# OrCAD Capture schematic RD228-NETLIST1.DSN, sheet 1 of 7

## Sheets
1 7: size A3
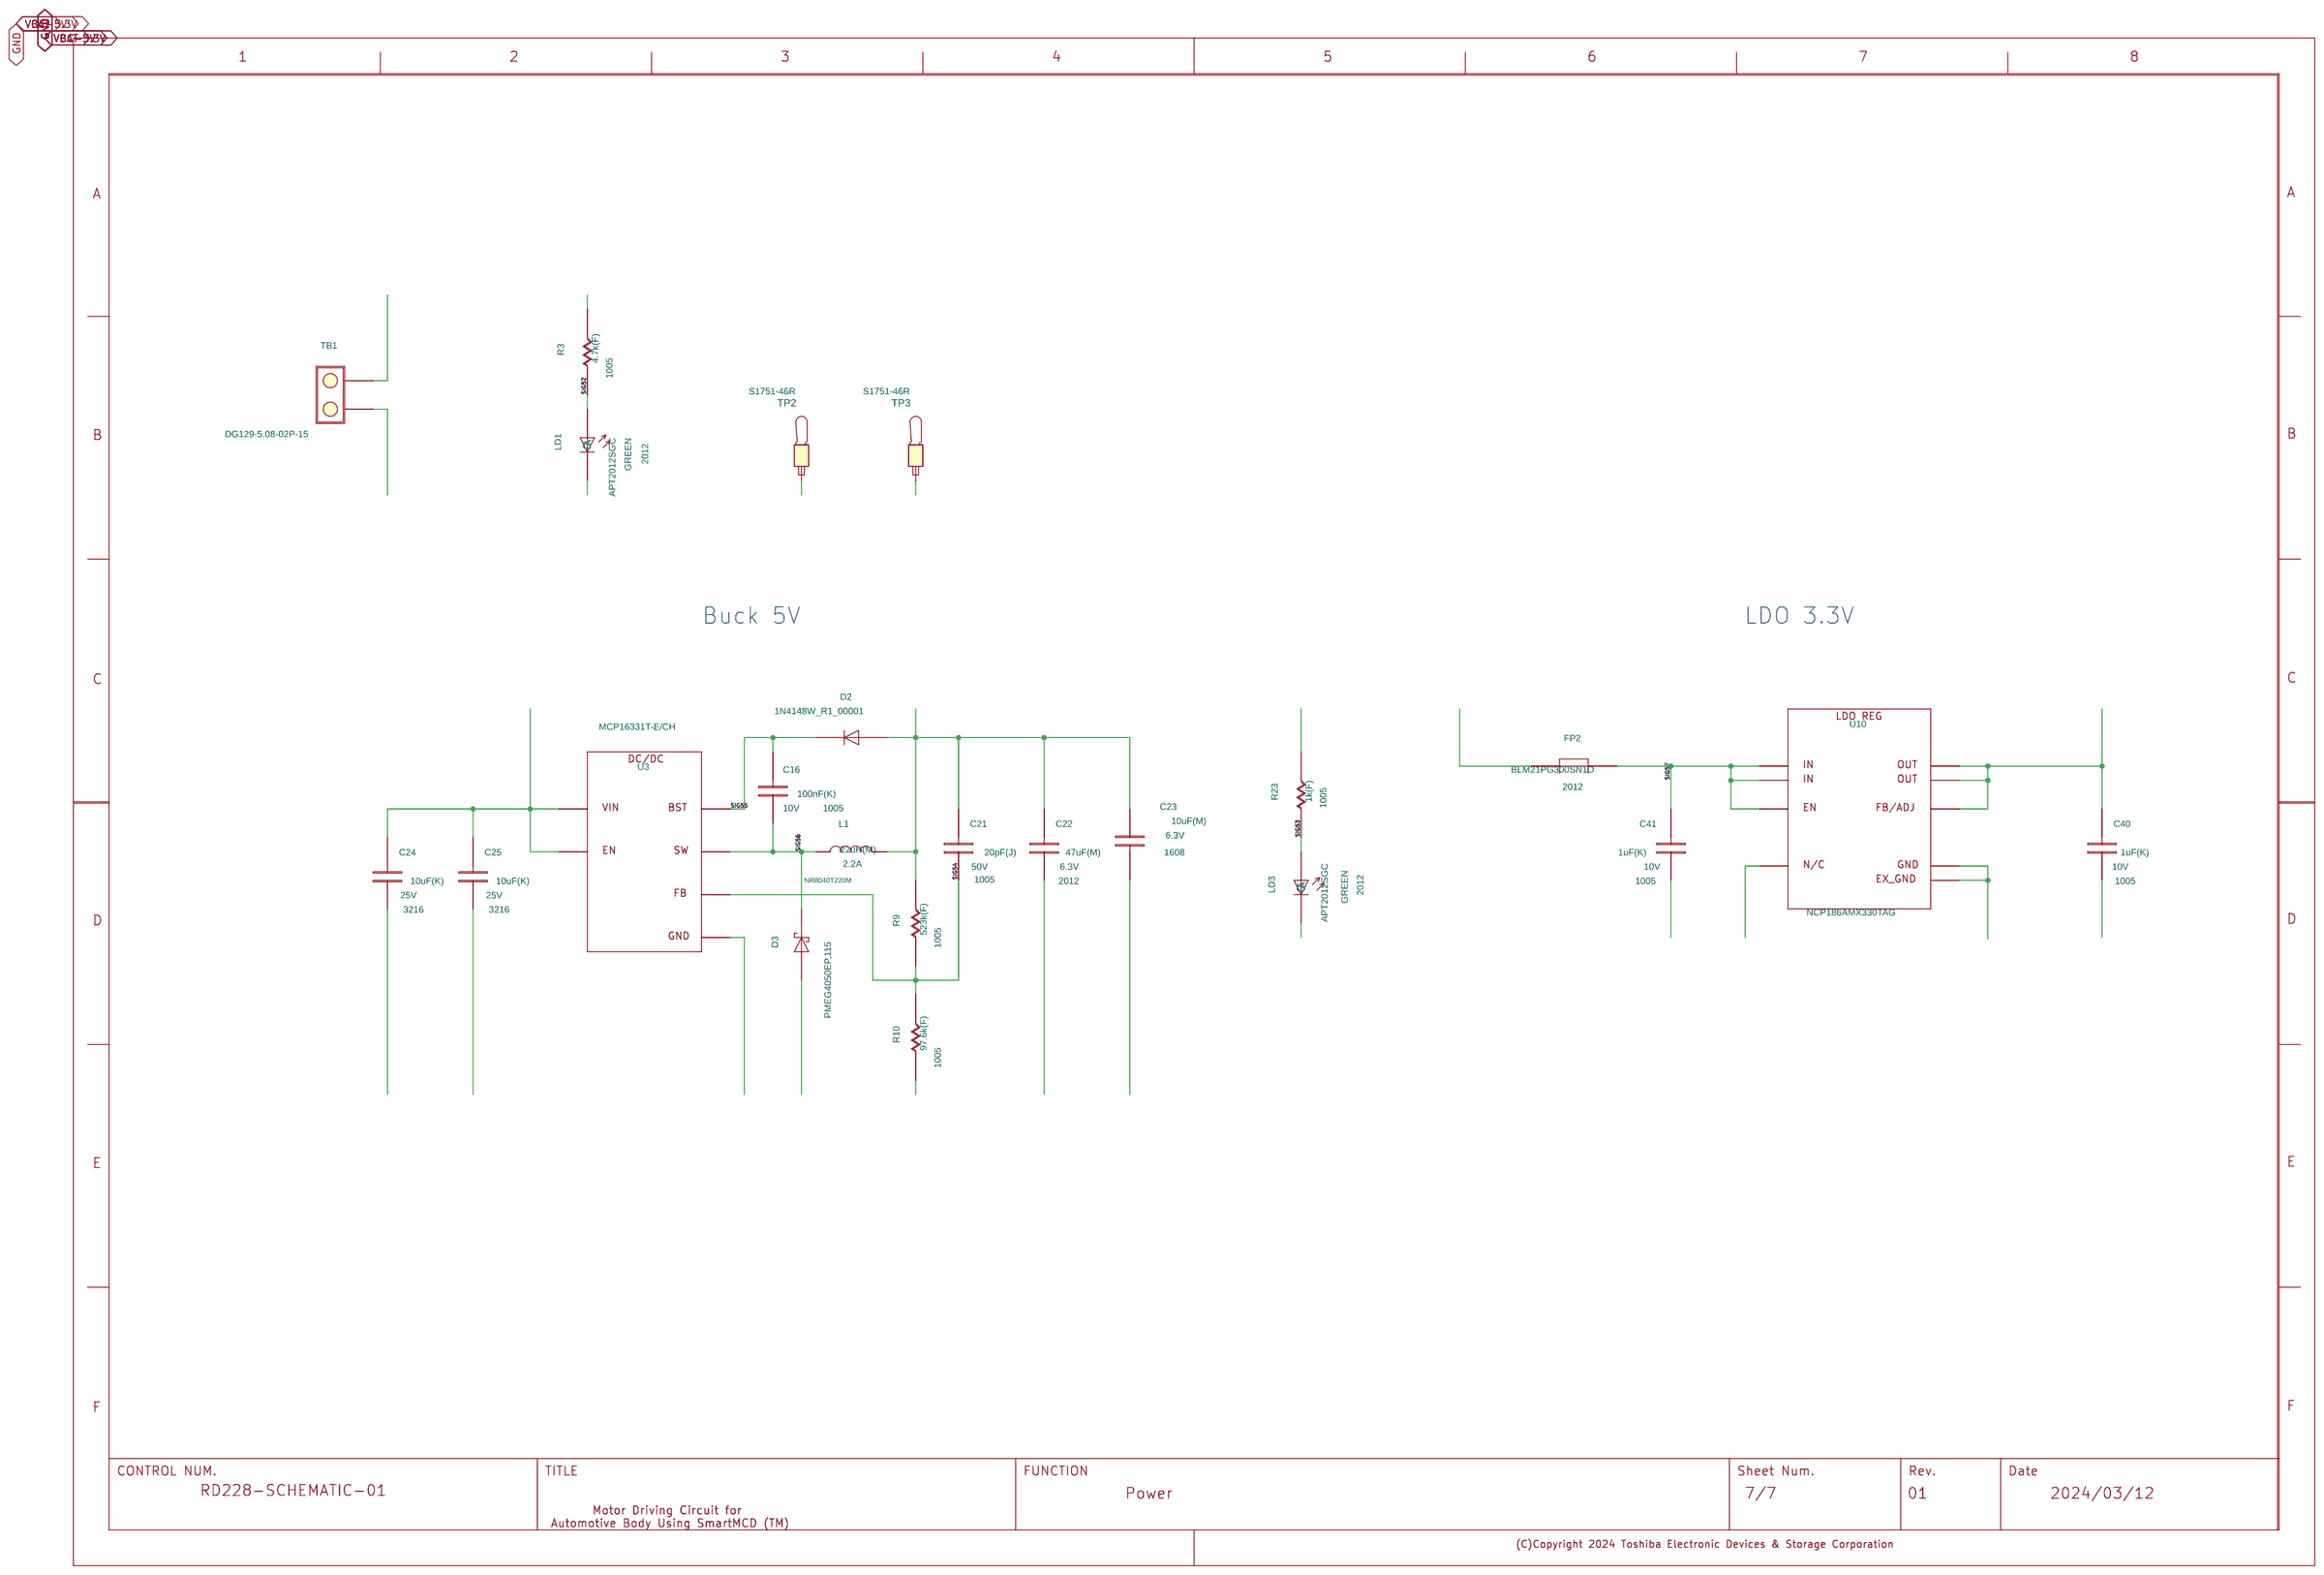
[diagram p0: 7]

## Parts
C16  100nF  [CAPC1005X55N-0402-NoOverlay]
C21  20pF  [CAPC1005X55N-0402-NoOverlay]
C22  47ƒÊF  [CAPC2013X100N-0805-NoOverlay]
C23  10ƒÊF  [CAPC1608X55N-0603-NoOverlay]
C24  10ƒÊF  [CAPC3216X140N-1206-NoOverlay]
C25  10ƒÊF  [CAPC3216X140N-1206-NoOverlay]
C40  1ƒÊF  [CAPC1005X55N-0402-NoOverlay]
C41  1ƒÊF  [CAPC1005X55N-0402-NoOverlay]
D2  NA  [SOD3716X135N-NoOverlay]
D3  NA  [DIOM5127X229N-SOD128-NoOverlay]
FP2  FERRITE  [INDC2213X140N-0805-NOOVERLAY]
L1  L
LD1  PWR  [DIOGREENC2013X120N-0805-NoOverlay]
LD3  3.3V  [DIOGREENC2013X120N-0805-NoOverlay]
R3  4.7k  [RESC1005X40N-0402-NOOVERLAY]
R9  523k  [RESC1005X40N-0402-NOOVERLAY]
R10  97.6k  [RESC1005X40N-0402-NOOVERLAY]
R23  1k  [RESC1005X40N-0402-NOOVERLAY]
TB1  DG129-5.08-02P-15  [SCREW_TERMINAL-5_08-F-2]
TP2  NA
TP3  NA
U3  MCP16331T  [SOT95P275X145-6L20N-SOT23-6-NoOverlay]
U10  NA  [SON40P120X45_HS-9N]
U?#7  WAKU_DEF100

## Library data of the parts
C16 = C: ASSEMBLY: SMD; AUTHOR: t5459927; BARCODE: 2911010025755; CATEGORY: Capacitors; COMP: Capacitor_Ceramic_C16; COMPONENTNAME: Capacitor_Ceramic_C16_Capacitor_Ceramic_C16; COMPONENTTYPE: 4; DATASHEET URL: http://ds.yuden.co.jp/TYCOMPAS/ut/detail.do?productNo; DATE: 2024/2/16; FAMILY: CERAMIC CAPACITOR; INSTANCENAME: INS4825; LAYOUTNAME: Z-cdca0044-bd23-4216-874f-abd41da06501.cmp23; MANUFACTURER: Taiyo Yuden; MANUFACTURER PART NUMBER: LMK105BJ104KV-F; NUMBER DEVICES IN PACKAGE: 1; PACKAGE CASE: 0402 (1005 Metric); PART TYPE: Capacitors; PIN NAMES ROTATE: True; PIN NAMES VISIBLE: False; PIN NUMBERS VISIBLE: False; RECOMMENDED RATING: Platinum; SAVECOUNT: 0; SIZECODESMD: 1005; TEMPERATURE COEFFICIENT: X5R; TIME: 16:56:57; TOLERANCE: }10%; UPDATEDATE: 2024/2/16; UPDATETIME: 16:56:57; UPDATEUSER: t5459927; VAL1: 100nF(K); VAL2: 10V; VAL3: LMK105BJ104KV-F; VOLTAGE RATED: 10V
C21 = C: ASSEMBLY: SMD; AUTHOR: t5459927; BARCODE: 0100000070406; CATEGORY: Capacitors; COMP: Capacitor_Ceramic_C21; COMPONENTNAME: Capacitor_Ceramic_C21_Capacitor_Ceramic_C21; COMPONENTTYPE: 4; DATASHEET URL: http://www.samsungsem.com/kr/support/product-search/mlcc/CL05C200JB5NNNC.jsp; DATE: 2024/2/16; FAMILY: CERAMIC CAPACITOR; ID: 8; INSTANCENAME: INS4815; ITEM_ID: 6192; LAYOUTNAME: Z-cdca0044-bd23-4216-874f-abd41da06501.cmp11; MANUFACTURER: Samsung Electro-Mechanics America, Inc.; MANUFACTURER PART NUMBER: CL05C200JB5NNNC; NUMBER DEVICES IN PACKAGE: 1; PACKAGE CASE: 0402 (1005 Metric); PART TYPE: Capacitors; PIN NAMES ROTATE: True; PIN NAMES VISIBLE: False; PIN NUMBERS VISIBLE: False; SAVECOUNT: 0; SIZECODESMD: 1005; TEMPERATURE COEFFICIENT: C0G, NP0; TIME: 16:56:43; TOLERANCE: }5%; UPDATEDATE: 2024/2/16; UPDATETIME: 16:56:43; UPDATEUSER: t5459927; VAL1: 20pF(J); VAL2: 50V; VAL3: CL05C200JB5NNNC; VOLTAGE RATED: 50V
C22 = C: ASSEMBLY: SMD; AUTHOR: t5459927; BARCODE: 3500000145772; CATEGORY: Capacitors; COMP: Capacitor_Ceramic_C22; COMPONENTNAME: Capacitor_Ceramic_C22_Capacitor_Ceramic_C22; COMPONENTTYPE: 4; DATASHEET URL: http://www.yageo.com/documents/recent/UPY-GPHC_X5R_4V-to-50V_24.pdf; DATE: 2024/2/16; FAMILY: CERAMIC CAPACITOR; ID: 427; INSTANCENAME: INS4835; ITEM_ID: 12714; LAYOUTNAME: Z-cdca0044-bd23-4216-874f-abd41da06501.cmp3; MANUFACTURER: Yageo; MANUFACTURER PART NUMBER: CC0805MKX5R5BB476; NUMBER DEVICES IN PACKAGE: 1; PACKAGE CASE: 0805 (2012 Metric); PART TYPE: Capacitors; PIN NAMES ROTATE: True; PIN NAMES VISIBLE: False; PIN NUMBERS VISIBLE: False; SAVECOUNT: 0; SIZECODESMD: 2012; TEMPERATURE COEFFICIENT: X5R; TIME: 16:56:48; TOLERANCE: }20%; UPDATEDATE: 2024/2/16; UPDATETIME: 16:56:48; UPDATEUSER: t5459927; VAL1: 47uF(M); VAL2: 6.3V; VAL3: CC0805MKX5R5BB476; VOLTAGE RATED: 6.3V
C23 = C: ASSEMBLY: SMD; AUTHOR: t5459927; BARCODE: 2911010042226; CATEGORY: Capacitors; COMP: Capacitor_Ceramic_C23; COMPONENTNAME: Capacitor_Ceramic_C23_Capacitor_Ceramic_C23; COMPONENTTYPE: 4; DATASHEET URL: http://www.samsungsem.com/kr/support/product-search/mlcc/CL10A106MQ8NNNL.jsp; DATE: 2024/2/16; FAMILY: CERAMIC CAPACITOR; ID: 31; INSTANCENAME: INS4845; ITEM_ID: 4902; MANUFACTURER: Samsung Electro-Mechanics America, Inc.; MANUFACTURER PART NUMBER: CL10A106MQ8NNNC; NUMBER DEVICES IN PACKAGE: 1; PACKAGE CASE: 0603 (1608 Metric); PART TYPE: Capacitors; PIN NAMES ROTATE: True; PIN NAMES VISIBLE: False; PIN NUMBERS VISIBLE: False; RECOMMENDED RATING: Platinum; SAVECOUNT: 0; SIZECODESMD: 1608; TEMPERATURE COEFFICIENT: X5R; TIME: 16:56:37; TOLERANCE: }20%; UPDATEDATE: 2024/2/16; UPDATETIME: 16:56:37; UPDATEUSER: t5459927; VAL1: 10uF(M); VAL2: 6.3V; VOLTAGE RATED: 6.3V
C24 = C: ASSEMBLY: SMD; AUTHOR: t5459927; BARCODE: 3500000176264; CATEGORY: Capacitors; COMP: Capacitor_Ceramic_C24; COMPONENTNAME: Capacitor_Ceramic_C24_Capacitor_Ceramic_C24; COMPONENTTYPE: 4; DATASHEET URL: https://www.yuden.co.jp/productdata/catalog/mlcc_all_e.pdf; DATE: 2024/2/16; FAMILY: CERAMIC CAPACITOR; ID: 617; INSTANCENAME: INS4865; ITEM_ID: 15761; LAYOUTNAME: Z-cdca0044-bd23-4216-874f-abd41da06501.cmp29; MANUFACTURER: Taiyo Yuden; MANUFACTURER PART NUMBER: TMK316B7106KL-TD; NUMBER DEVICES IN PACKAGE: 1; PACKAGE CASE: 1206 (3216 Metric); PART TYPE: Capacitors; PIN NAMES ROTATE: True; PIN NAMES VISIBLE: False; PIN NUMBERS VISIBLE: False; SAVECOUNT: 0; SIZECODESMD: 3216; TEMPERATURE COEFFICIENT: X7R; TIME: 16:56:41; TOLERANCE: }10%; UPDATEDATE: 2024/2/16; UPDATETIME: 16:56:41; UPDATEUSER: t5459927; VAL1: 10uF(K); VAL2: 25V; VAL3: TMK316B7106KL-TD; VOLTAGE RATED: 25V
C25 = C: ASSEMBLY: SMD; AUTHOR: t5459927; BARCODE: 3500000176264; CATEGORY: Capacitors; COMP: Capacitor_Ceramic_C25; COMPONENTNAME: Capacitor_Ceramic_C25_Capacitor_Ceramic_C25; COMPONENTTYPE: 4; DATASHEET URL: https://www.yuden.co.jp/productdata/catalog/mlcc_all_e.pdf; DATE: 2024/2/16; FAMILY: CERAMIC CAPACITOR; ID: 617; INSTANCENAME: INS4875; ITEM_ID: 15761; LAYOUTNAME: Z-cdca0044-bd23-4216-874f-abd41da06501.cmp26; MANUFACTURER: Taiyo Yuden; MANUFACTURER PART NUMBER: TMK316B7106KL-TD; NUMBER DEVICES IN PACKAGE: 1; PACKAGE CASE: 1206 (3216 Metric); PART TYPE: Capacitors; PIN NAMES ROTATE: True; PIN NAMES VISIBLE: False; PIN NUMBERS VISIBLE: False; SAVECOUNT: 0; SIZECODESMD: 3216; TEMPERATURE COEFFICIENT: X7R; TIME: 16:56:55; TOLERANCE: }10%; UPDATEDATE: 2024/2/16; UPDATETIME: 16:56:55; UPDATEUSER: t5459927; VAL1: 10uF(K); VAL2: 25V; VAL3: TMK316B7106KL-TD; VOLTAGE RATED: 25V
C40 = C: ASSEMBLY: SMD; AUTHOR: t5459927; BARCODE: 2911010025762; CATEGORY: Capacitors; COMP: Capacitor_Ceramic_C40; COMPONENTNAME: Capacitor_Ceramic_C40_Capacitor_Ceramic_C40; COMPONENTTYPE: 4; DATASHEET URL: http://ds.yuden.co.jp/TYCOMPAS/ut/detail.do?productNo; DATE: 2024/2/16; FAMILY: CERAMIC CAPACITOR; ID: 62; INSTANCENAME: INS5645; ITEM_ID: 3485; LAYOUTNAME: Z-cdca0044-bd23-4216-874f-abd41da06501.cmp36; MANUFACTURER: Taiyo Yuden; MANUFACTURER PART NUMBER: LMK105BJ105KV-F; NUMBER DEVICES IN PACKAGE: 1; PACKAGE CASE: 0402 (1005 Metric); PART TYPE: Capacitors; PIN NAMES ROTATE: True; PIN NAMES VISIBLE: False; PIN NUMBERS VISIBLE: False; SAVECOUNT: 0; SIZECODESMD: 1005; TEMPERATURE COEFFICIENT: X5R; TIME: 16:56:39; TOLERANCE: }10%; UPDATEDATE: 2024/2/16; UPDATETIME: 16:56:39; UPDATEUSER: t5459927; VAL1: 1uF(K); VAL2: 10V; VOLTAGE RATED: 10V
C41 = C: ASSEMBLY: SMD; AUTHOR: t5459927; BARCODE: 2911010025762; CATEGORY: Capacitors; COMP: Capacitor_Ceramic_C41; COMPONENTNAME: Capacitor_Ceramic_C41_Capacitor_Ceramic_C41; COMPONENTTYPE: 4; DATASHEET URL: http://ds.yuden.co.jp/TYCOMPAS/ut/detail.do?productNo; DATE: 2024/2/16; FAMILY: CERAMIC CAPACITOR; ID: 62; INSTANCENAME: INS5655; ITEM_ID: 3485; LAYOUTNAME: Z-cdca0044-bd23-4216-874f-abd41da06501.cmp33; MANUFACTURER: Taiyo Yuden; MANUFACTURER PART NUMBER: LMK105BJ105KV-F; NUMBER DEVICES IN PACKAGE: 1; PACKAGE CASE: 0402 (1005 Metric); PART TYPE: Capacitors; PIN NAMES ROTATE: True; PIN NAMES VISIBLE: False; PIN NUMBERS VISIBLE: False; SAVECOUNT: 0; SIZECODESMD: 1005; TEMPERATURE COEFFICIENT: X5R; TIME: 16:56:53; TOLERANCE: }10%; UPDATEDATE: 2024/2/16; UPDATETIME: 16:56:53; UPDATEUSER: t5459927; VAL1: 1uF(K); VAL2: 10V; VAL3: LMK105BJ105KV-F; VOLTAGE RATED: 10V
D2 = DIODE: ASSEMBLY: SMD; BARCODE: 3500000205278; COMP: DIODE_D2; COMPONENTNAME: DIODE_D2_DIODE_D2; COMPONENTTYPE: 4; CURRENT  AVERAGE RECTIFIED: 300mA (DC); DATASHEET URL: https://www.datasheets360.com/pdf/-7889717499515636739; DIODE TYPE: Standard; ID: 469; INSTANCENAME: INS4807; ITEM_ID: 18663; LAYOUTNAME: Z-cdca0044-bd23-4216-874f-abd41da06501.cmp12; MANUFACTURER: Pan Jit; MANUFACTURER PART NUMBER: 1N4148W_R1_00001; NUMBER DEVICES IN PACKAGE: 1; PACKAGE CASE: SOD-123; PART TYPE: Discrete Semiconductors; PIN NAMES ROTATE: True; PIN NAMES VISIBLE: False; PIN NUMBERS VISIBLE: False; SPEED: Small Signal; UPDATEDATE: 2024/2/22; UPDATETIME: 17:58:41; UPDATEUSER: w20165dm; VAL1: 1N4148W_R1_00001; VAL3: 1N4148W_R1_00001; VOLTAGE  DC REVERSE: 100V
D3 = DIODE_SCHOTTKY: ASSEMBLY: SMD; BARCODE: 3500000159731; CATEGORY: Discrete Semiconductor Products; COMP: Diode_Schottky_D3; COMPONENTNAME: Diode_Schottky_D3_Diode_Schottky_D3; COMPONENTTYPE: 4; CURRENT  AVERAGE RECTIFIED: 5A; DATASHEET URL: http://assets.nexperia.com/documents/data-sheet/PMEG4050EP.pdf; DIODE TYPE: Schottky; FAMILY: DIODE; ID: 295; INSTANCENAME: INS4855; ITEM_ID: 14109; LAYOUTNAME: Z-cdca0044-bd23-4216-874f-abd41da06501.cmp8; MANUFACTURER: Nexperia USA Inc.; MANUFACTURER PART NUMBER: PMEG4050EP,115; NUMBER DEVICES IN PACKAGE: 1; PACKAGE CASE: SOD-128; PART TYPE: Discrete Semiconductors; PIN NAMES ROTATE: True; PIN NAMES VISIBLE: False; PIN NUMBERS VISIBLE: False; SPEED: Fast Recovery; UPDATEDATE: 2024/2/21; UPDATETIME: 16:02:20; UPDATEUSER: w20165dm; VAL1: PMEG4050EP,115; VAL3: PMEG4050EP,115
FP2 = FL08A: ASSEMBLY: SMD; BARCODE: 3500000137531; CATEGORY: Filters; COMP: FERRITE_FP2; COMPONENTNAME: FERRITE_FP2_FERRITE_FP2; COMPONENTTYPE: 4; DATASHEET URL: http://search.murata.co.jp/Ceramy/image/img/PDF/ENG/L0110S0100BLM21P.pdf; FILTER TYPE: Power Line; ID: 134; IMPEDANCE FREQUENCY: 30 Ohm @ 100MHz; INSTANCENAME: INS5515; ITEM_ID: 11886; LAYOUTNAME: Z-cdca0044-bd23-4216-874f-abd41da06501.cmp17; MANUFACTURER: Murata Electronics North America; MANUFACTURER PART NUMBER: BLM21PG300SN1D; NUMBER DEVICES IN PACKAGE: 1; PACKAGE CASE: 0805 (2012 Metric); PART TYPE: Inductor, Transf, Filter, Ferrite; PIN NAMES ROTATE: True; PIN NAMES VISIBLE: False; PIN NUMBERS VISIBLE: False; SIZECODESMD: 2012; VAL3: BLM21PG300SN1D
L1 = L: COMPONENTTYPE: 4; VAL1: 22uH(M); VAL2: 2.2A; VAL3: NR8040T220M
LD1 = LED: ASSEMBLY: SMD; BARCODE: 2911010024338; CATEGORY: Optoelectronics; COMP: LED_GREEN_LD1; COMPONENTNAME: LED_GREEN_LD1_LED_GREEN_LD1; COMPONENTTYPE: 4; DATASHEET URL: http://www.kingbrightusa.com/images/catalog/SPEC/APT2012SGC.pdf; ID: 28; INSTANCENAME: INS4739; ITEM_ID: 3342; LAYOUTNAME: Z-cdca0044-bd23-4216-874f-abd41da06501.cmp41; LENS COLOR: Colorless; LENS TRANSPARENCY: Clear; MANUFACTURER: Kingbright; MANUFACTURER PART NUMBER: APT2012SGC; NUMBER DEVICES IN PACKAGE: 1; PACKAGE CASE: 0805 (2012 Metric); PART TYPE: Optoelectronics; PIN NAMES ROTATE: True; PIN NAMES VISIBLE: False; PIN NUMBERS VISIBLE: False; SIZECODESMD: 2012; VAL1: GREEN; VAL3: APT2012SGC; VOLTAGE FORWARD: 2.2V; WAVELENGTH: 568nm
LD3 = LED_GREEN: ASSEMBLY: SMD; BARCODE: 2911010024338; CATEGORY: Optoelectronics; COMP: LED_GREEN_LD3; COMPONENTNAME: LED_GREEN_LD3_LED_GREEN_LD3; COMPONENTTYPE: 4; DATASHEET URL: http://www.kingbrightusa.com/images/catalog/SPEC/APT2012SGC.pdf; FAMILY: LED; ID: 28; INSTANCENAME: INS4541; ITEM_ID: 3342; LAYOUTNAME: Z-cdca0044-bd23-4216-874f-abd41da06501.cmp43; LENS COLOR: Colorless; LENS TRANSPARENCY: Clear; MANUFACTURER: Kingbright; MANUFACTURER PART NUMBER: APT2012SGC; NUMBER DEVICES IN PACKAGE: 1; PACKAGE CASE: 0805 (2012 Metric); PART TYPE: Optoelectronics; PIN NAMES ROTATE: True; PIN NAMES VISIBLE: False; PIN NUMBERS VISIBLE: False; SIZECODESMD: 2012; VAL1: GREEN; VAL3: APT2012SGC; VOLTAGE FORWARD: 2.2V; WAVELENGTH: 568nm
R3 = R: ASSEMBLY: SMD; AUTHOR: t5459927; BARCODE: 2911010042394; CATEGORY: Resistors; COMP: Resistor_R3; COMPONENTNAME: Resistor_R3_Resistor_R3; COMPONENTTYPE: 4; DATASHEET URL: http://www.yageo.com/NewPortal/yageodocoutput?fileName; DATE: 2024/2/16; FAMILY: RESISTOR; ID: 44; INSTANCENAME: INS5471; ITEM_ID: 4919; LAYOUTNAME: Z-cdca0044-bd23-4216-874f-abd41da06501.cmp7; MANUFACTURER: Yageo; MANUFACTURER PART NUMBER: RC0402FR-074K7L; NUMBER DEVICES IN PACKAGE: 1; PACKAGE CASE: 0402 (1005 Metric); PART TYPE: Resistors; PIN NAMES ROTATE: True; PIN NAMES VISIBLE: False; PIN NUMBERS VISIBLE: False; POWER: 0.063W, 1/16W; RECOMMENDED RATING: Gold; SAVECOUNT: 0; SIZECODESMD: 1005; TEMPERATURE COEFFICIENT: }100ppm/C; TIME: 16:56:57; TOLERANCE: }1%; UPDATEDATE: 2024/2/16; UPDATETIME: 16:56:57; UPDATEUSER: t5459927; VAL1: 4.7k(F); VAL2: 63mW; VAL3: RC0402FR-074K7L
R9 = R: ASSEMBLY: SMD; AUTHOR: t5459927; BARCODE: 3500000182531; CATEGORY: Resistors; COMP: Resistor_R9; COMPONENTNAME: Resistor_R9_Resistor_R9; COMPONENTTYPE: 4; DATASHEET URL: http://www.yageo.com/documents/recent/PYu-RC_Group_51_RoHS_L_9.pdf; DATE: 2024/2/16; FAMILY: RESISTOR; INSTANCENAME: INS5451; LAYOUTNAME: Z-cdca0044-bd23-4216-874f-abd41da06501.cmp42; MANUFACTURER: Yageo; MANUFACTURER PART NUMBER: RC0402FR-07523KL; NUMBER DEVICES IN PACKAGE: 1; PACKAGE CASE: 0402 (1005 Metric); PART TYPE: Resistors; PIN NAMES ROTATE: True; PIN NAMES VISIBLE: False; PIN NUMBERS VISIBLE: False; POWER: 0.063W, 1/16W; SAVECOUNT: 0; SIZECODESMD: 1005; TEMPERATURE COEFFICIENT: }100ppm/C; TIME: 16:56:53; TOLERANCE: }1%; UPDATEDATE: 2024/2/16; UPDATETIME: 16:56:53; UPDATEUSER: t5459927; VAL1: 523k(F); VAL2: 63mW; VAL3: RC0402FR-07523KL
R10 = R: ASSEMBLY: SMD; AUTHOR: t5459927; BARCODE: 3500000182555; CATEGORY: Resistors; COMP: Resistor_R10; COMPONENTNAME: Resistor_R10_Resistor_R10; COMPONENTTYPE: 4; DATASHEET URL: http://www.yageo.com/documents/recent/PYu-RC_Group_51_RoHS_L_9.pdf; DATE: 2024/2/16; FAMILY: RESISTOR; INSTANCENAME: INS5461; LAYOUTNAME: Z-cdca0044-bd23-4216-874f-abd41da06501.cmp19; MANUFACTURER: Yageo; MANUFACTURER PART NUMBER: RC0402FR-07523KL; NUMBER DEVICES IN PACKAGE: 1; PACKAGE CASE: 0402 (1005 Metric); PART TYPE: Resistors; PIN NAMES ROTATE: True; PIN NAMES VISIBLE: False; PIN NUMBERS VISIBLE: False; POWER: 0.063W, 1/16W; SAVECOUNT: 0; SIZECODESMD: 1005; TEMPERATURE COEFFICIENT: }100ppm/C; TIME: 16:56:42; TOLERANCE: }1%; UPDATEDATE: 2024/2/16; UPDATETIME: 16:56:42; UPDATEUSER: t5459927; VAL1: 97.6k(F); VAL2: 63mW
R23 = R: ASSEMBLY: SMD; AUTHOR: t5459927; BARCODE: 2911010036768; CATEGORY: Resistors; COMP: Resistor_R23; COMPONENTNAME: Resistor_R23_Resistor_R23; COMPONENTTYPE: 4; DATASHEET URL: http://www.yageo.com/NewPortal/yageodocoutput?fileName; DATE: 2024/2/16; FAMILY: RESISTOR; ID: 72; INSTANCENAME: INS4531; ITEM_ID: 4337; LAYOUTNAME: Z-cdca0044-bd23-4216-874f-abd41da06501.cmp10; MANUFACTURER: Yageo; MANUFACTURER PART NUMBER: RC0402FR-071KL; NUMBER DEVICES IN PACKAGE: 1; PACKAGE CASE: 0402 (1005 Metric); PART TYPE: Resistors; PIN NAMES ROTATE: True; PIN NAMES VISIBLE: False; PIN NUMBERS VISIBLE: False; POWER: 0.063W, 1/16W; SAVECOUNT: 0; SIZECODESMD: 1005; TEMPERATURE COEFFICIENT: }100ppm/C; TIME: 16:56:50; TOLERANCE: }1%; UPDATEDATE: 2024/2/16; UPDATETIME: 16:56:50; UPDATEUSER: t5459927; VAL1: 1k(F); VAL2: 63mW; VAL3: RC0402FR-071KL
TB1 = SCREW_TERMINAL_2P: ASSEMBLY: TH; BARCODE: 0100000007334; COMP: SCREW_TERMINAL_2P_TB1; COMPONENTNAME: SCREW_TERMINAL_2P_TB1_SCREW_TERMINAL_2P_TB1; COMPONENTTYPE: 4; CURRENT RATING: 20A; DATASHEET URL: http://www.tme.eu/html/EN/degson-pcb-angled-terminal-blocks-pitch-5-mm-h_18-mm/ramka_4315_EN_pelny.html; FAMILY: TERMINAL BLOCK; ID: 123; INSTANCENAME: INS5807; ITEM_ID: 1010; LAYOUTNAME: Z-cdca0044-bd23-4216-874f-abd41da06501.cmp15; MANUFACTURER: Degson Electronics; MOUNTING TYPE: Through Hole; NUMBER DEVICES IN PACKAGE: 1; PART TYPE: Connectors, Electromechanical; PIN NAMES ROTATE: True; PIN NAMES VISIBLE: False; PIN NUMBERS VISIBLE: False; PITCH: 5.08mm
TP2 = TEST_POINT_SMD_TP2: COMPONENTTYPE: 4; LAYOUTNAME: Z-cdca0044-bd23-4216-874f-abd41da06501.cmp61; VAL3: S1751-46R
TP3 = TEST_POINT_SMD_TP2: COMPONENTTYPE: 4; LAYOUTNAME: Z-cdca0044-bd23-4216-874f-abd41da06501.cmp62; VAL3: S1751-46R
U3 = MCP16331T: ASSEMBLY: SMD; BARCODE: 0100000130339; CATEGORY: Integrated Circuits (ICs); COMP: MCP16331T_E_CH_U3; COMPONENTNAME: MCP16331T_E_CH_U3_MCP16331T_E_CH_U3; COMPONENTTYPE: 4; CURRENT  OUTPUT: 500mA; DATASHEET URL: http://www.microchip.com/mymicrochip/filehandler.aspx?ddocname; FAMILY: Voltage Regulators - DC DC Switching Regulators; FUNCTION: Step-Down; ID: 992; INSTANCENAME: INS4789; ITEM_ID: 11148; LAYOUTNAME: Z-cdca0044-bd23-4216-874f-abd41da06501.cmp9; MANUFACTURER: Microchip Technology; MANUFACTURER PART NUMBER: MCP16331T-E/CH; NUMBER DEVICES IN PACKAGE: 1; NUMBER OF OUTPUTS: 1; OUTPUT CONFIGURATION: Positive; OUTPUT TYPE: Adjustable; PACKAGE CASE: SOT-23-6; PART TYPE: Integrated Circuits; PIN NAMES ROTATE: True; PIN NAMES VISIBLE: True; PIN NUMBERS VISIBLE: True; TOPOLOGY: Buck; VAL1: MCP16331T-E/CH; VAL3: MCP16331T-E/CH; VOLTAGE  INPUT MAX: 50V; VOLTAGE  INPUT MIN: 4.4V
U10 = NCP186AMX330TAG: ASSEMBLY: SMD; BARCODE: 3500000269829; CATEGORY: Integrated Circuits (ICs); COMP: NCP186AMX330TAG_U10; COMPONENTNAME: NCP186AMX330TAG_U10_NCP186AMX330TAG_U10; COMPONENTTYPE: 4; CURRENT  OUTPUT: 1A; DATASHEET URL: https://www.onsemi.com/pub/Collateral/NCP186-D.PDF; FAMILY: Voltage Regulators - Linear; HIDDENNETNAME: GND; ID: 2966; INSTANCENAME: INS5491; ITEM_ID: 24127; LAYOUTNAME: Z-cdca0044-bd23-4216-874f-abd41da06501.cmp45; MANUFACTURER: ON Semiconductor; NUMBER DEVICES IN PACKAGE: 1; PACKAGE CASE: 8-XFDFN Exposed Pad; PART TYPE: Integrated Circuits; PIN NAMES ROTATE: True; PIN NAMES VISIBLE: False; PIN NUMBERS VISIBLE: False; VOLTAGE  INPUT: MAX - 5.5V; VOLTAGE  OUTPUT: 3.3V
U?#7 = WAKU_DEF100: AUTHOR: w20165dm; COMPONENTTYPE: 2; DATE: 2024/03/12; DRAWINGNUMBER: RD228-SCHEMATIC-01; FUNCTION: Power; LAYOUTNAME: Z-cdca0044-bd23-4216-874f-abd41da06501.cmp46; REVISION: 01; SAVEAREA0: 185750,-43960,448537,75779; SAVECOUNT: 9; SHEETNUMBER: 7/7; SHTSAVECOUNT: 29; TIME: 13:12:30; TITLE: Motor Driving Circuit for / Automotive Body Using SmartMCD (TM); UPDATEDATE: 2024/03/18; UPDATETIME: 15:38:53

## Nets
GND: C21.2 C22.1 C22.2 C23.1 C23.2 C24.1 C25.1 C40.1 C41.1 D2.2 D3.2 FP2.1 L1.2 LD1.1(C) LD3.1(C) R9.2 R10.1 TB1.1 TP2.1(GND) TP3.1(GND) U3.2 U10.3 U10.5 U10.9 ; also on sheet 2 3 4 5 6 7
VBAT: C24.2 C25.2 R3.2 TB1.2 U3.4 U3.5 ; also on sheet 2 7
VCC-3.3V: C40.2 R23.2 U10.1 U10.2 U10.4 ; also on sheet 4
SIG52: LD1.2(A) R3.1
SIG53: LD3.2(A) R23.1
SIG54: C21.1 R9.1 R10.2 U3.3
SIG55: C16.2 D2.1 U3.1
SIG56: C16.1 D3.1 L1.1 U3.6
SIG57: C41.2 FP2.2 U10.6 U10.7 U10.8

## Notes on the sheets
sheet 1
- Buck 5V
- LDO 3.3V
